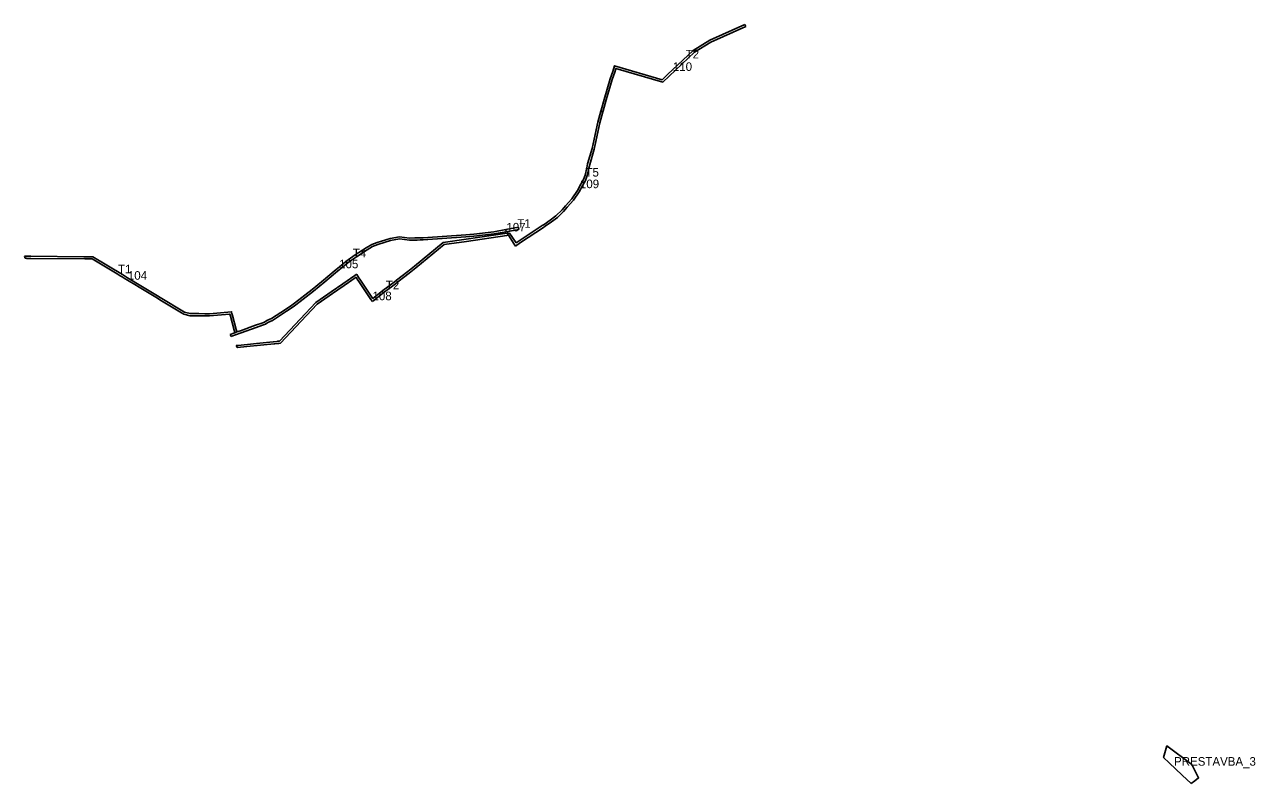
# Model space of a CAD drawing. Extents: x -477001 to -465642, y -1158278 to -1150672.
# Drawn here: x -476390 to -474673, y -1155448 to -1154388 of the extents above; entities that cross this region are included whole.
import ezdxf

# ---------------------------------------------------------------- set-up
doc = ezdxf.new("R2010")
doc.units = 0
for name, color, linetype in [('prestavba_n', 7, 'Continuous'), ('VPS_id', 7, 'Continuous'), ('VPS_n', 7, 'Continuous'), ('vyvlastneni_n', 7, 'Continuous')]:
    doc.layers.add(name, color=color, linetype=linetype)

msp = doc.modelspace()

# ---------------------------------------------------------------- linework, layer by layer
at = {"layer": 'prestavba_n'}
for p, q in [((-474774.8, -1155435.9), (-474762.3, -1155447.6)), ((-474762.3, -1155447.6), (-474757.2, -1155443.9))]:
    msp.add_line(p, q, dxfattribs=at)
for points in [[(-474761.2, -1155421.4), (-474796, -1155395.4), (-474800.8, -1155411.6), (-474792.9, -1155418.9), (-474774.8, -1155435.9)], [(-474757.2, -1155443.9), (-474751.9, -1155440), (-474761.2, -1155421.4)]]:
    msp.add_lwpolyline(points, dxfattribs=at)
at = {"layer": 'VPS_n'}
for p, q in [((-475383.8, -1154391.2), (-475385, -1154388.5)), ((-475583, -1154510), (-475585.9, -1154509.2)), ((-475585.9, -1154509.2), (-475583, -1154510)), ((-475866.8, -1154684.6), (-475879.9, -1154687)), ((-475716.5, -1154679.8), (-475773.7, -1154688.1)), ((-475773.3, -1154691.1), (-475717, -1154682.9)), ((-475718.5, -1154674.5), (-475735, -1154677.5)), ((-475700.9, -1154671.4), (-475718.5, -1154674.5)), ((-475718.5, -1154674.5), (-475717.9, -1154677.5)), ((-475717.9, -1154677.5), (-475718.5, -1154674.5)), ((-475717.9, -1154677.5), (-475700.4, -1154674.4)), ((-475717, -1154682.9), (-475714.7, -1154682.6)), ((-475713.2, -1154679.4), (-475716.5, -1154679.8)), ((-475715.3, -1154681.7), (-475716.5, -1154679.8)), ((-475716.5, -1154679.8), (-475715.3, -1154681.7)), ((-475714.7, -1154682.6), (-475715.3, -1154681.7)), ((-475715.3, -1154681.7), (-475714.7, -1154682.6)), ((-475714.7, -1154682.6), (-475706.7, -1154695)), ((-475704.2, -1154693.3), (-475713.2, -1154679.4)), ((-475700.4, -1154674.4), (-475700.9, -1154671.4)), ((-475835.3, -1154686), (-475845.5, -1154686.3)), ((-475842.4, -1154689.2), (-475838.2, -1154689.1)), ((-475706.7, -1154695), (-475705, -1154697.5)), ((-476389.9, -1154711.7), (-476389.1, -1154714.7)), ((-475957.9, -1154732.6), (-475972.9, -1154745.2)), ((-475945.4, -1154722.5), (-475957.9, -1154732.6)), ((-475856.9, -1154734.6), (-475863.1, -1154739.3)), ((-475853.2, -1154735.6), (-475843.9, -1154727.9)), ((-476249.5, -1154743.4), (-476246.3, -1154745.3)), ((-476243, -1154743.8), (-476246.3, -1154741.8)), ((-476230, -1154751.6), (-476243, -1154743.8)), ((-476232.4, -1154753.7), (-476204.7, -1154770.4)), ((-476204.3, -1154767.1), (-476230, -1154751.6)), ((-475972.9, -1154745.2), (-475988.6, -1154758.2)), ((-475945.7, -1154750.2), (-475962, -1154761.4)), ((-475960.3, -1154763.9), (-475944, -1154752.7)), ((-475929.1, -1154738.7), (-475945.7, -1154750.2)), ((-475944, -1154752.7), (-475927.5, -1154741.2)), ((-475926.6, -1154737), (-475929.1, -1154738.7)), ((-475927.5, -1154741.2), (-475926, -1154743.6)), ((-475926.5, -1154737.1), (-475926.6, -1154737)), ((-475926, -1154743.6), (-475923.7, -1154747)), ((-475923.7, -1154747), (-475906.6, -1154772.2)), ((-475863.1, -1154739.3), (-475871, -1154745.3)), ((-476204.7, -1154770.4), (-476201.2, -1154772.5)), ((-476200.8, -1154769.3), (-476204.3, -1154767.1)), ((-475988.6, -1154758.2), (-476013.5, -1154777.4)), ((-475962, -1154761.4), (-475977.6, -1154772.2)), ((-475975.8, -1154774.6), (-475960.3, -1154763.9)), ((-476017, -1154780.2), (-476025.9, -1154786)), ((-476013.5, -1154777.4), (-476017, -1154780.2)), ((-475906.6, -1154772.2), (-475904.7, -1154775.1)), ((-476102.7, -1154795.3), (-476097.4, -1154815.1)), ((-476099.9, -1154794.4), (-476100.6, -1154791.5)), ((-476094.6, -1154814.1), (-476099.9, -1154794.4)), ((-476055.3, -1154803.8), (-476059, -1154805.1)), ((-476051.8, -1154801.7), (-476055.3, -1154803.8)), ((-476097.8, -1154819), (-476103.1, -1154820.9)), ((-476096.5, -1154818.6), (-476097.8, -1154819)), ((-476097.4, -1154815.1), (-476096.7, -1154818.1)), ((-476096.7, -1154818.1), (-476096.5, -1154818.6)), ((-476093.7, -1154817.5), (-476096.5, -1154818.6)), ((-476096.5, -1154818.6), (-476093.7, -1154817.5)), ((-476095.8, -1154821.5), (-476087.6, -1154818.5)), ((-476093.8, -1154817), (-476094.6, -1154814.1)), ((-476093.7, -1154817.5), (-476093.8, -1154817)), ((-476088.6, -1154815.7), (-476093.7, -1154817.5)), ((-476093.9, -1154836.4), (-476094.6, -1154836.5)), ((-476094.6, -1154836.5), (-476093.1, -1154839.1)), ((-476092.1, -1154836.2), (-476093.9, -1154836.4)), ((-476093.1, -1154839.1), (-476092.7, -1154839.3)), ((-476092.7, -1154839.3), (-476080, -1154838)), ((-476066.3, -1154833.5), (-476092.1, -1154836.2)), ((-476080, -1154838), (-476041.9, -1154834)), ((-476043.3, -1154831.2), (-476066.3, -1154833.5)), ((-476042.7, -1154831.1), (-476043.3, -1154831.2)), ((-476037.6, -1154830.6), (-476042.7, -1154831.1)), ((-476041.9, -1154834), (-476041, -1154833.9)), ((-476041, -1154833.9), (-476036.3, -1154833.5)), ((-476036.8, -1154830.5), (-476037.6, -1154830.6)), ((-476036.3, -1154833.5), (-476035.2, -1154833.4))]:
    msp.add_line(p, q, dxfattribs=at)
for points in [[(-475385, -1154388.5), (-475434, -1154410.4), (-475457.1, -1154424.4), (-475492.7, -1154458.1), (-475500.4, -1154465.5), (-475567, -1154445.8), (-475569.4, -1154454.1), (-475572.8, -1154464.1), (-475581.5, -1154492.9), (-475585.6, -1154508), (-475585.9, -1154509.2)], [(-475583, -1154510), (-475582.7, -1154508.7), (-475578.7, -1154493.7), (-475569.9, -1154465), (-475566.6, -1154455), (-475565, -1154449.5), (-475499.6, -1154468.8), (-475490.6, -1154460.3), (-475455.3, -1154426.8), (-475432.6, -1154413.1), (-475383.8, -1154391.2)], [(-475705, -1154697.5), (-475698.2, -1154692.8), (-475666.1, -1154671.6), (-475663.4, -1154669.9), (-475654.6, -1154663.8), (-475646.6, -1154657.6), (-475638, -1154649.2), (-475632.9, -1154643.5), (-475624, -1154633.6), (-475616.1, -1154621.8), (-475611, -1154612.8), (-475607.4, -1154605.9), (-475605.1, -1154599.3), (-475602.7, -1154588.9), (-475601.5, -1154583.5), (-475595, -1154562.1), (-475593.7, -1154555.6), (-475587.2, -1154525.5), (-475583, -1154510)], [(-475585.9, -1154509.2), (-475590.1, -1154524.8), (-475596.6, -1154555), (-475597.9, -1154561.4), (-475604.4, -1154582.8), (-475605.6, -1154588.2), (-475608, -1154598.5), (-475610.2, -1154604.7), (-475613.7, -1154611.3), (-475618.7, -1154620.2), (-475626.4, -1154631.8), (-475635.2, -1154641.5), (-475640.1, -1154647.2), (-475648.5, -1154655.4), (-475656.4, -1154661.3), (-475665.1, -1154667.4), (-475667.8, -1154669.1), (-475699.9, -1154690.4), (-475704.2, -1154693.3)], [(-475845.5, -1154686.3), (-475852.8, -1154686.5), (-475866.8, -1154684.6)], [(-475838.2, -1154689.1), (-475833.7, -1154689), (-475774.2, -1154684.9), (-475762.9, -1154684), (-475734.6, -1154680.5), (-475717.9, -1154677.5)], [(-475735, -1154677.5), (-475763.2, -1154681), (-475774.5, -1154681.9), (-475833.9, -1154686), (-475835.3, -1154686)], [(-476087.6, -1154818.5), (-476066.7, -1154811.1), (-476057.9, -1154807.9), (-476054, -1154806.5), (-476050.4, -1154804.4), (-476044.1, -1154801.4), (-476024.3, -1154788.5), (-476015.2, -1154782.6), (-476011.6, -1154779.8), (-475986.8, -1154760.5), (-475970.9, -1154747.5), (-475956, -1154734.9), (-475943.5, -1154724.8), (-475939.6, -1154721.6), (-475936.5, -1154719.1), (-475927, -1154712.4), (-475911.8, -1154702.8), (-475904.3, -1154698.1), (-475897, -1154695.4), (-475879.2, -1154689.9), (-475866.7, -1154687.6), (-475852.9, -1154689.5), (-475842.4, -1154689.2)], [(-475905.6, -1154695.4), (-475913.4, -1154700.2), (-475928.7, -1154709.9), (-475938.4, -1154716.7)], [(-475879.9, -1154687), (-475898, -1154692.6), (-475905.6, -1154695.4)], [(-475773.7, -1154688.1), (-475806, -1154692.7), (-475845.8, -1154725.6)], [(-475843.9, -1154727.9), (-475804.7, -1154695.6), (-475773.3, -1154691.1)], [(-476387.6, -1154711.7), (-476388.7, -1154711.7), (-476389.9, -1154711.7)], [(-476389.1, -1154714.7), (-476387.9, -1154714.7), (-476386.8, -1154714.8)], [(-476381.3, -1154711.8), (-476384.3, -1154711.8), (-476387.6, -1154711.7)], [(-476386.8, -1154714.8), (-476384, -1154714.8), (-476381, -1154714.8)], [(-476306.7, -1154712.4), (-476307.3, -1154712.4), (-476381.3, -1154711.8)], [(-476381, -1154714.8), (-476305.7, -1154715.4), (-476305.5, -1154715.4)], [(-476302.7, -1154712.4), (-476303.5, -1154712.4), (-476306.7, -1154712.4)], [(-476305.5, -1154715.4), (-476301.5, -1154715.4), (-476301.1, -1154715.4)], [(-476253.5, -1154737.5), (-476294.9, -1154712.5), (-476302.7, -1154712.4)], [(-476301.1, -1154715.4), (-476295.8, -1154715.5), (-476260.9, -1154736.5), (-476256.5, -1154739.2)], [(-475938.4, -1154716.7), (-475941.5, -1154719.3), (-475945.4, -1154722.5)], [(-475872.7, -1154750.6), (-475869.2, -1154747.6), (-475853.2, -1154735.6)], [(-475845.8, -1154725.6), (-475855.1, -1154733.2), (-475856.9, -1154734.6)], [(-476256.5, -1154739.2), (-476253.9, -1154740.7), (-476249.5, -1154743.4)], [(-476246.3, -1154741.8), (-476250.6, -1154739.2), (-476253.5, -1154737.5)], [(-476246.3, -1154745.3), (-476234, -1154752.8), (-476232.4, -1154753.7)], [(-475921.3, -1154745.1), (-475923.5, -1154741.9), (-475926.5, -1154737.1)], [(-475904.3, -1154770.3), (-475921.2, -1154745.3), (-475921.3, -1154745.1)], [(-475904.7, -1154775.1), (-475888.3, -1154762.1), (-475872.7, -1154750.6)], [(-475871, -1154745.3), (-475874.5, -1154748.2), (-475890.1, -1154759.7), (-475904, -1154770.7), (-475904.1, -1154770.5), (-475904.3, -1154770.3)], [(-476149.1, -1154791.9), (-476158.6, -1154791.8), (-476163.1, -1154790.7), (-476166.8, -1154789.8), (-476200.8, -1154769.3)], [(-476201.2, -1154772.5), (-476173.1, -1154789.4), (-476167.9, -1154792.6), (-476159, -1154794.8), (-476148.8, -1154794.9)], [(-476025.9, -1154786), (-476045.6, -1154798.7), (-476051.8, -1154801.7)], [(-475977.6, -1154772.2), (-475983.5, -1154776.3), (-476005.6, -1154799.7)], [(-476004, -1154802.4), (-475981.5, -1154778.6), (-475975.8, -1154774.6)], [(-476100.6, -1154791.5), (-476101.1, -1154789.7), (-476101.2, -1154789.3), (-476131.9, -1154792.1), (-476138.6, -1154792), (-476146.9, -1154791.9), (-476148.2, -1154791.9), (-476149.1, -1154791.9)], [(-476148.8, -1154794.9), (-476131.8, -1154795.1), (-476103.9, -1154792.5), (-476103.8, -1154792.5)], [(-476103.8, -1154792.5), (-476103.5, -1154792.5), (-476102.7, -1154795.3)], [(-476059, -1154805.1), (-476067.7, -1154808.2), (-476088.6, -1154815.7)], [(-476005.6, -1154799.7), (-476034.4, -1154830.2), (-476036.8, -1154830.5)], [(-476035.2, -1154833.4), (-476033, -1154833.1), (-476004, -1154802.4)], [(-476103.1, -1154820.9), (-476102.8, -1154822.1), (-476101.9, -1154823.7)], [(-476101.9, -1154823.7), (-476097, -1154821.9), (-476095.8, -1154821.5)]]:
    msp.add_lwpolyline(points, dxfattribs=at)
at = {"layer": 'vyvlastneni_n'}
for p, q in [((-475383.8, -1154391.2), (-475385, -1154388.5)), ((-475583, -1154510), (-475585.9, -1154509.2)), ((-475585.9, -1154509.2), (-475583, -1154510)), ((-475866.8, -1154684.6), (-475879.9, -1154687)), ((-475716.5, -1154679.8), (-475773.7, -1154688.1)), ((-475773.3, -1154691.1), (-475717, -1154682.9)), ((-475718.5, -1154674.5), (-475735, -1154677.5)), ((-475700.9, -1154671.4), (-475718.5, -1154674.5)), ((-475718.5, -1154674.5), (-475717.9, -1154677.5)), ((-475717.9, -1154677.5), (-475718.5, -1154674.5)), ((-475717.9, -1154677.5), (-475700.4, -1154674.4)), ((-475717, -1154682.9), (-475714.7, -1154682.6)), ((-475713.2, -1154679.4), (-475716.5, -1154679.8)), ((-475715.3, -1154681.7), (-475716.5, -1154679.8)), ((-475716.5, -1154679.8), (-475715.3, -1154681.7)), ((-475714.7, -1154682.6), (-475715.3, -1154681.7)), ((-475715.3, -1154681.7), (-475714.7, -1154682.6)), ((-475714.7, -1154682.6), (-475706.7, -1154695)), ((-475704.2, -1154693.3), (-475713.2, -1154679.4)), ((-475700.4, -1154674.4), (-475700.9, -1154671.4)), ((-475835.3, -1154686), (-475845.5, -1154686.3)), ((-475842.4, -1154689.2), (-475838.2, -1154689.1)), ((-475706.7, -1154695), (-475705, -1154697.5)), ((-476389.9, -1154711.7), (-476389.1, -1154714.7)), ((-475957.9, -1154732.6), (-475972.9, -1154745.2)), ((-475945.4, -1154722.5), (-475957.9, -1154732.6)), ((-475856.9, -1154734.6), (-475863.1, -1154739.3)), ((-475853.2, -1154735.6), (-475843.9, -1154727.9)), ((-476249.5, -1154743.4), (-476246.3, -1154745.3)), ((-476243, -1154743.8), (-476246.3, -1154741.8)), ((-476230, -1154751.6), (-476243, -1154743.8)), ((-476232.4, -1154753.7), (-476204.7, -1154770.4)), ((-476204.3, -1154767.1), (-476230, -1154751.6)), ((-475972.9, -1154745.2), (-475988.6, -1154758.2)), ((-475945.7, -1154750.2), (-475962, -1154761.4)), ((-475960.3, -1154763.9), (-475944, -1154752.7)), ((-475929.1, -1154738.7), (-475945.7, -1154750.2)), ((-475944, -1154752.7), (-475927.5, -1154741.2)), ((-475926.6, -1154737), (-475929.1, -1154738.7)), ((-475927.5, -1154741.2), (-475926, -1154743.6)), ((-475926.5, -1154737.1), (-475926.6, -1154737)), ((-475926, -1154743.6), (-475923.7, -1154747)), ((-475923.7, -1154747), (-475906.6, -1154772.2)), ((-475863.1, -1154739.3), (-475871, -1154745.3)), ((-476204.7, -1154770.4), (-476201.2, -1154772.5)), ((-476200.8, -1154769.3), (-476204.3, -1154767.1)), ((-475988.6, -1154758.2), (-476013.5, -1154777.4)), ((-475962, -1154761.4), (-475977.6, -1154772.2)), ((-475975.8, -1154774.6), (-475960.3, -1154763.9)), ((-476017, -1154780.2), (-476025.9, -1154786)), ((-476013.5, -1154777.4), (-476017, -1154780.2)), ((-475906.6, -1154772.2), (-475904.7, -1154775.1)), ((-476102.7, -1154795.3), (-476097.4, -1154815.1)), ((-476099.9, -1154794.4), (-476100.6, -1154791.5)), ((-476094.6, -1154814.1), (-476099.9, -1154794.4)), ((-476055.3, -1154803.8), (-476059, -1154805.1)), ((-476051.8, -1154801.7), (-476055.3, -1154803.8)), ((-476097.8, -1154819), (-476103.1, -1154820.9)), ((-476096.5, -1154818.6), (-476097.8, -1154819)), ((-476097.4, -1154815.1), (-476096.7, -1154818.1)), ((-476096.7, -1154818.1), (-476096.5, -1154818.6)), ((-476093.7, -1154817.5), (-476096.5, -1154818.6)), ((-476096.5, -1154818.6), (-476093.7, -1154817.5)), ((-476095.8, -1154821.5), (-476087.6, -1154818.5)), ((-476093.8, -1154817), (-476094.6, -1154814.1)), ((-476093.7, -1154817.5), (-476093.8, -1154817)), ((-476088.6, -1154815.7), (-476093.7, -1154817.5)), ((-476093.9, -1154836.4), (-476094.6, -1154836.5)), ((-476094.6, -1154836.5), (-476093.1, -1154839.1)), ((-476092.1, -1154836.2), (-476093.9, -1154836.4)), ((-476093.1, -1154839.1), (-476092.7, -1154839.3)), ((-476092.7, -1154839.3), (-476080, -1154838)), ((-476066.3, -1154833.5), (-476092.1, -1154836.2)), ((-476080, -1154838), (-476041.9, -1154834)), ((-476043.3, -1154831.2), (-476066.3, -1154833.5)), ((-476042.7, -1154831.1), (-476043.3, -1154831.2)), ((-476037.6, -1154830.6), (-476042.7, -1154831.1)), ((-476041.9, -1154834), (-476041, -1154833.9)), ((-476041, -1154833.9), (-476036.3, -1154833.5)), ((-476036.8, -1154830.5), (-476037.6, -1154830.6)), ((-476036.3, -1154833.5), (-476035.2, -1154833.4))]:
    msp.add_line(p, q, dxfattribs=at)
for points in [[(-475385, -1154388.5), (-475434, -1154410.4), (-475457.1, -1154424.4), (-475492.7, -1154458.1), (-475500.4, -1154465.5), (-475567, -1154445.8), (-475569.4, -1154454.1), (-475572.8, -1154464.1), (-475581.5, -1154492.9), (-475585.6, -1154508), (-475585.9, -1154509.2)], [(-475583, -1154510), (-475582.7, -1154508.7), (-475578.7, -1154493.7), (-475569.9, -1154465), (-475566.6, -1154455), (-475565, -1154449.5), (-475499.6, -1154468.8), (-475490.6, -1154460.3), (-475455.3, -1154426.8), (-475432.6, -1154413.1), (-475383.8, -1154391.2)], [(-475705, -1154697.5), (-475698.2, -1154692.8), (-475666.1, -1154671.6), (-475663.4, -1154669.9), (-475654.6, -1154663.8), (-475646.6, -1154657.6), (-475638, -1154649.2), (-475632.9, -1154643.5), (-475624, -1154633.6), (-475616.1, -1154621.8), (-475611, -1154612.8), (-475607.4, -1154605.9), (-475605.1, -1154599.3), (-475602.7, -1154588.9), (-475601.5, -1154583.5), (-475595, -1154562.1), (-475593.7, -1154555.6), (-475587.2, -1154525.5), (-475583, -1154510)], [(-475585.9, -1154509.2), (-475590.1, -1154524.8), (-475596.6, -1154555), (-475597.9, -1154561.4), (-475604.4, -1154582.8), (-475605.6, -1154588.2), (-475608, -1154598.5), (-475610.2, -1154604.7), (-475613.7, -1154611.3), (-475618.7, -1154620.2), (-475626.4, -1154631.8), (-475635.2, -1154641.5), (-475640.1, -1154647.2), (-475648.5, -1154655.4), (-475656.4, -1154661.3), (-475665.1, -1154667.4), (-475667.8, -1154669.1), (-475699.9, -1154690.4), (-475704.2, -1154693.3)], [(-475845.5, -1154686.3), (-475852.8, -1154686.5), (-475866.8, -1154684.6)], [(-475838.2, -1154689.1), (-475833.7, -1154689), (-475774.2, -1154684.9), (-475762.9, -1154684), (-475734.6, -1154680.5), (-475717.9, -1154677.5)], [(-475735, -1154677.5), (-475763.2, -1154681), (-475774.5, -1154681.9), (-475833.9, -1154686), (-475835.3, -1154686)], [(-476087.6, -1154818.5), (-476066.7, -1154811.1), (-476057.9, -1154807.9), (-476054, -1154806.5), (-476050.4, -1154804.4), (-476044.1, -1154801.4), (-476024.3, -1154788.5), (-476015.2, -1154782.6), (-476011.6, -1154779.8), (-475986.8, -1154760.5), (-475970.9, -1154747.5), (-475956, -1154734.9), (-475943.5, -1154724.8), (-475939.6, -1154721.6), (-475936.5, -1154719.1), (-475927, -1154712.4), (-475911.8, -1154702.8), (-475904.3, -1154698.1), (-475897, -1154695.4), (-475879.2, -1154689.9), (-475866.7, -1154687.6), (-475852.9, -1154689.5), (-475842.4, -1154689.2)], [(-475905.6, -1154695.4), (-475913.4, -1154700.2), (-475928.7, -1154709.9), (-475938.4, -1154716.7)], [(-475879.9, -1154687), (-475898, -1154692.6), (-475905.6, -1154695.4)], [(-475773.7, -1154688.1), (-475806, -1154692.7), (-475845.8, -1154725.6)], [(-475843.9, -1154727.9), (-475804.7, -1154695.6), (-475773.3, -1154691.1)], [(-476387.6, -1154711.7), (-476388.7, -1154711.7), (-476389.9, -1154711.7)], [(-476389.1, -1154714.7), (-476387.9, -1154714.7), (-476386.8, -1154714.8)], [(-476381.3, -1154711.8), (-476384.3, -1154711.8), (-476387.6, -1154711.7)], [(-476386.8, -1154714.8), (-476384, -1154714.8), (-476381, -1154714.8)], [(-476306.7, -1154712.4), (-476307.3, -1154712.4), (-476381.3, -1154711.8)], [(-476381, -1154714.8), (-476305.7, -1154715.4), (-476305.5, -1154715.4)], [(-476302.7, -1154712.4), (-476303.5, -1154712.4), (-476306.7, -1154712.4)], [(-476305.5, -1154715.4), (-476301.5, -1154715.4), (-476301.1, -1154715.4)], [(-476253.5, -1154737.5), (-476294.9, -1154712.5), (-476302.7, -1154712.4)], [(-476301.1, -1154715.4), (-476295.8, -1154715.5), (-476260.9, -1154736.5), (-476256.5, -1154739.2)], [(-475938.4, -1154716.7), (-475941.5, -1154719.3), (-475945.4, -1154722.5)], [(-475872.7, -1154750.6), (-475869.2, -1154747.6), (-475853.2, -1154735.6)], [(-475845.8, -1154725.6), (-475855.1, -1154733.2), (-475856.9, -1154734.6)], [(-476256.5, -1154739.2), (-476253.9, -1154740.7), (-476249.5, -1154743.4)], [(-476246.3, -1154741.8), (-476250.6, -1154739.2), (-476253.5, -1154737.5)], [(-476246.3, -1154745.3), (-476234, -1154752.8), (-476232.4, -1154753.7)], [(-475921.3, -1154745.1), (-475923.5, -1154741.9), (-475926.5, -1154737.1)], [(-475904.3, -1154770.3), (-475921.2, -1154745.3), (-475921.3, -1154745.1)], [(-475904.7, -1154775.1), (-475888.3, -1154762.1), (-475872.7, -1154750.6)], [(-475871, -1154745.3), (-475874.5, -1154748.2), (-475890.1, -1154759.7), (-475904, -1154770.7), (-475904.1, -1154770.5), (-475904.3, -1154770.3)], [(-476149.1, -1154791.9), (-476158.6, -1154791.8), (-476163.1, -1154790.7), (-476166.8, -1154789.8), (-476200.8, -1154769.3)], [(-476201.2, -1154772.5), (-476173.1, -1154789.4), (-476167.9, -1154792.6), (-476159, -1154794.8), (-476148.8, -1154794.9)], [(-476025.9, -1154786), (-476045.6, -1154798.7), (-476051.8, -1154801.7)], [(-475977.6, -1154772.2), (-475983.5, -1154776.3), (-476005.6, -1154799.7)], [(-476004, -1154802.4), (-475981.5, -1154778.6), (-475975.8, -1154774.6)], [(-476100.6, -1154791.5), (-476101.1, -1154789.7), (-476101.2, -1154789.3), (-476131.9, -1154792.1), (-476138.6, -1154792), (-476146.9, -1154791.9), (-476148.2, -1154791.9), (-476149.1, -1154791.9)], [(-476148.8, -1154794.9), (-476131.8, -1154795.1), (-476103.9, -1154792.5), (-476103.8, -1154792.5)], [(-476103.8, -1154792.5), (-476103.5, -1154792.5), (-476102.7, -1154795.3)], [(-476059, -1154805.1), (-476067.7, -1154808.2), (-476088.6, -1154815.7)], [(-476005.6, -1154799.7), (-476034.4, -1154830.2), (-476036.8, -1154830.5)], [(-476035.2, -1154833.4), (-476033, -1154833.1), (-476004, -1154802.4)], [(-476103.1, -1154820.9), (-476102.8, -1154822.1), (-476101.9, -1154823.7)], [(-476101.9, -1154823.7), (-476097, -1154821.9), (-476095.8, -1154821.5)]]:
    msp.add_lwpolyline(points, dxfattribs=at)

# ---------------------------------------------------------------- texts
at = {"layer": 'prestavba_n'}
msp.add_text('PRESTAVBA_3', height=12, dxfattribs=at).set_placement((-474786.1, -1155422.9))
at = {"layer": 'VPS_id'}
for s, p in [('110', (-475485.4, -1154453.1)), ('109', (-475615.1, -1154616.8)), ('107', (-475717.7, -1154677.2)), ('105', (-475951, -1154728.6)), ('104', (-476245.8, -1154744.6)), ('108', (-475904.5, -1154773.2))]:
    msp.add_text(s, height=12, dxfattribs=at).set_placement(p)
at = {"layer": 'VPS_n'}
for s, p in [('T2', (-475467.6, -1154435.7)), ('T5', (-475607.4, -1154600.6)), ('T1', (-475702.5, -1154672.1)), ('T4', (-475932, -1154713.4)), ('T1', (-476259.7, -1154735.7)), ('T2', (-475885.9, -1154758.1))]:
    msp.add_text(s, height=12, dxfattribs=at).set_placement(p)

doc.saveas('drawing.dxf')
